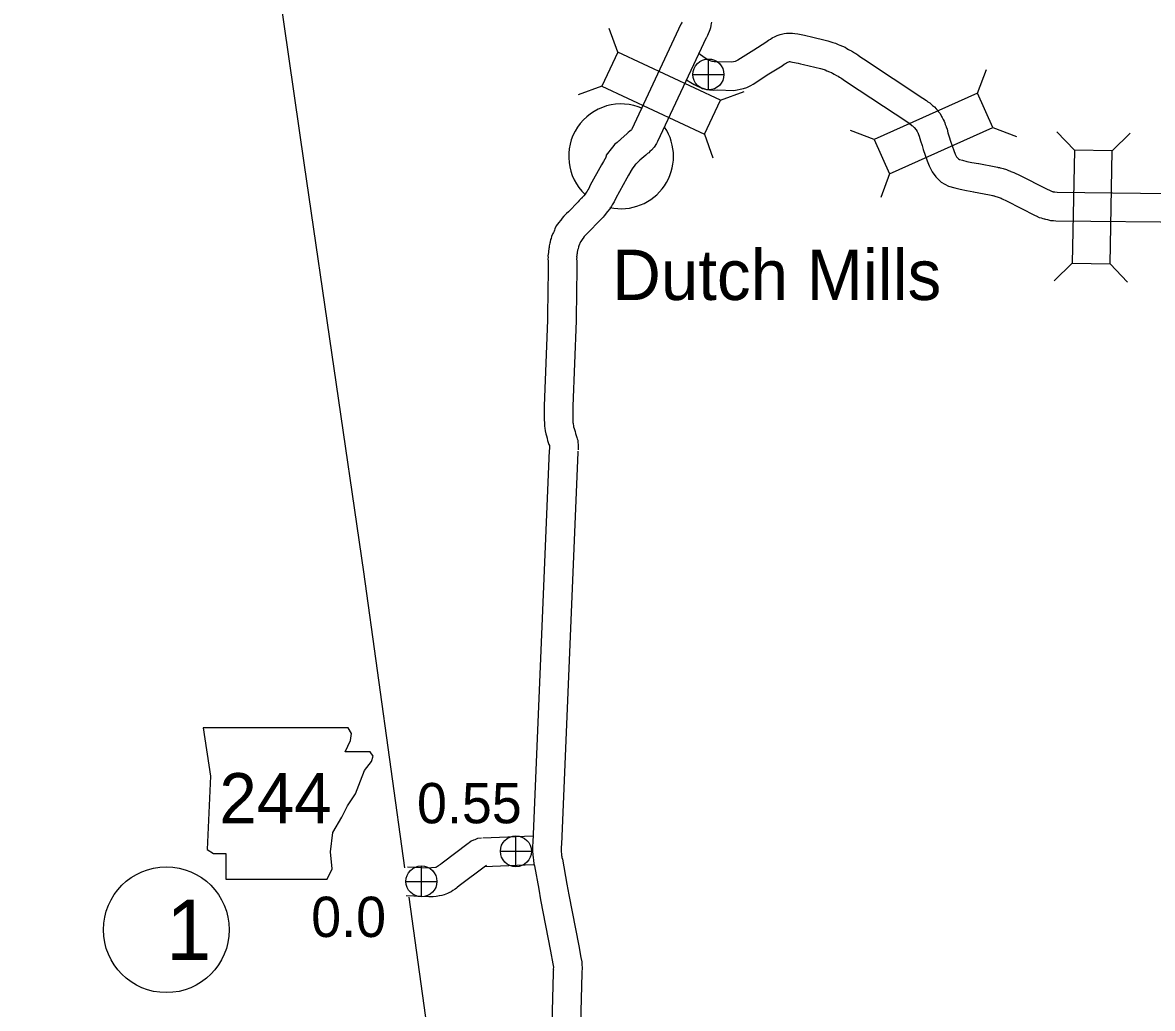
# Model space of a CAD drawing. Extents: x -939622 to -934245, y 1383184 to 1385301.
# Drawn here: x -936492.99 to -936457.42, y 1384824.91 to 1384855.94 of the extents above; entities that cross this region are included whole.
import ezdxf

# ---------------------------------------------------------------- set-up
doc = ezdxf.new("R2010")
doc.units = 0
for name, color, linetype in [('1', 7, 'Continuous'), ('10', 7, 'Continuous'), ('20', 7, 'Continuous'), ('21', 7, 'Continuous'), ('24', 7, 'Continuous'), ('25', 7, 'Continuous'), ('26', 7, 'Continuous'), ('27', 7, 'Continuous')]:
    doc.layers.add(name, color=color, linetype=linetype)

msp = doc.modelspace()

# ---------------------------------------------------------------- linework, layer by layer
at = {"layer": '1'}
for points in [[(-936484.111, 1384851.453), (-936491.245, 1384900.95), (-936492.986, 1384912.484)], [(-936480.949, 1384829.338), (-936482.239, 1384838.65), (-936484.111, 1384851.453)], [(-936478.373, 1384810.747), (-936480.821, 1384828.415)]]:
    msp.add_lwpolyline(points, dxfattribs=at)
at = {"layer": '10'}
for points in [[(-936472.227, 1384855.956), (-936472.234, 1384855.942), (-936472.239, 1384855.933), (-936472.262, 1384855.897), (-936473.811, 1384852.588), (-936473.82, 1384852.57), (-936473.83, 1384852.562), (-936473.873, 1384852.523), (-936473.922, 1384852.48), (-936473.966, 1384852.437), (-936474.145, 1384852.286), (-936474.211, 1384852.226), (-936474.231, 1384852.206), (-936474.27, 1384852.172), (-936474.338, 1384852.113), (-936474.412, 1384852.023), (-936474.615, 1384851.765), (-936474.629, 1384851.702)], [(-936471.299, 1384855.956), (-936471.306, 1384855.916), (-936471.317, 1384855.851), (-936471.336, 1384855.776), (-936471.356, 1384855.711), (-936471.376, 1384855.66), (-936471.402, 1384855.595), (-936471.431, 1384855.536), (-936471.461, 1384855.478), (-936471.473, 1384855.46), (-936472.998, 1384852.202), (-936473.031, 1384852.134), (-936473.1, 1384852.017), (-936473.19, 1384851.924), (-936473.239, 1384851.883), (-936473.278, 1384851.848), (-936473.312, 1384851.818), (-936473.363, 1384851.769), (-936473.551, 1384851.609), (-936473.586, 1384851.578), (-936473.614, 1384851.549), (-936473.681, 1384851.492), (-936473.69, 1384851.484), (-936473.71, 1384851.459), (-936473.737, 1384851.424), (-936473.774, 1384851.372), (-936473.777, 1384851.369), (-936473.846, 1384851.256)], [(-936471.684, 1384854.97), (-936471.65, 1384854.943), (-936471.575, 1384854.884), (-936471.466, 1384854.816), (-936471.413, 1384854.781), (-936471.376, 1384854.765), (-936471.326, 1384854.742), (-936471.285, 1384854.729), (-936471.273, 1384854.726), (-936471.212, 1384854.721), (-936471.107, 1384854.722), (-936470.668, 1384854.709), (-936470.543, 1384854.734), (-936470.501, 1384854.755), (-936470.485, 1384854.761), (-936470.471, 1384854.77), (-936469.972, 1384855.089), (-936469.588, 1384855.327), (-936469.507, 1384855.389), (-936469.446, 1384855.423), (-936469.393, 1384855.459), (-936469.294, 1384855.508), (-936469.233, 1384855.533), (-936469.135, 1384855.572), (-936469.057, 1384855.59), (-936469.017, 1384855.599), (-936468.937, 1384855.613), (-936468.873, 1384855.614), (-936468.812, 1384855.615), (-936468.746, 1384855.61), (-936468.679, 1384855.602), (-936468.579, 1384855.585), (-936468.373, 1384855.543), (-936468.294, 1384855.524), (-936468.199, 1384855.502), (-936467.635, 1384855.37), (-936467.482, 1384855.322), (-936467.393, 1384855.293), (-936467.314, 1384855.257), (-936467.259, 1384855.235), (-936467.181, 1384855.206), (-936467.097, 1384855.165), (-936467.038, 1384855.131), (-936466.983, 1384855.099), (-936466.943, 1384855.075), (-936466.889, 1384855.05), (-936466.794, 1384854.99), (-936466.755, 1384854.966), (-936466.691, 1384854.927), (-936466.63, 1384854.881), (-936466.516, 1384854.803), (-936464.643, 1384853.568), (-936464.529, 1384853.486), (-936464.489, 1384853.453), (-936464.431, 1384853.421), (-936464.353, 1384853.345), (-936464.343, 1384853.336), (-936464.278, 1384853.289), (-936464.226, 1384853.225), (-936464.18, 1384853.176), (-936464.163, 1384853.15), (-936464.106, 1384853.086), (-936464.056, 1384852.988), (-936464.039, 1384852.953), (-936464.004, 1384852.897), (-936463.979, 1384852.837), (-936463.96, 1384852.783), (-936463.945, 1384852.74), (-936463.928, 1384852.698), (-936463.917, 1384852.67), (-936463.913, 1384852.662)], [(-936472.097, 1384854.149), (-936472.092, 1384854.145), (-936471.953, 1384854.06), (-936471.849, 1384853.99), (-936471.741, 1384853.942), (-936471.646, 1384853.9), (-936471.543, 1384853.867), (-936471.453, 1384853.842), (-936471.368, 1384853.831), (-936471.243, 1384853.82), (-936471.115, 1384853.822), (-936470.594, 1384853.806), (-936470.297, 1384853.865), (-936470.191, 1384853.904), (-936470.123, 1384853.937), (-936470.067, 1384853.962), (-936469.992, 1384854.008), (-936469.493, 1384854.327), (-936469.074, 1384854.586), (-936469.013, 1384854.634), (-936468.973, 1384854.656), (-936468.937, 1384854.681), (-936468.922, 1384854.688), (-936468.894, 1384854.699), (-936468.867, 1384854.71), (-936468.862, 1384854.711), (-936468.849, 1384854.714), (-936468.837, 1384854.714), (-936468.831, 1384854.714), (-936468.808, 1384854.711), (-936468.746, 1384854.7), (-936468.567, 1384854.664), (-936468.501, 1384854.648), (-936468.404, 1384854.626), (-936467.874, 1384854.502), (-936467.756, 1384854.464), (-936467.719, 1384854.452), (-936467.67, 1384854.43), (-936467.581, 1384854.394), (-936467.533, 1384854.376), (-936467.52, 1384854.37), (-936467.488, 1384854.352), (-936467.441, 1384854.325), (-936467.366, 1384854.279), (-936467.318, 1384854.257), (-936467.273, 1384854.229), (-936467.227, 1384854.2), (-936467.195, 1384854.18), (-936467.154, 1384854.15), (-936467.019, 1384854.057), (-936465.154, 1384852.827), (-936465.08, 1384852.774), (-936464.999, 1384852.707), (-936464.974, 1384852.693), (-936464.919, 1384852.644), (-936464.854, 1384852.572), (-936464.828, 1384852.519), (-936464.812, 1384852.493), (-936464.808, 1384852.48), (-936464.786, 1384852.421), (-936464.765, 1384852.368)], [(-936464.765, 1384852.368), (-936464.724, 1384852.223)], [(-936463.913, 1384852.662), (-936463.887, 1384852.587)], [(-936463.887, 1384852.587), (-936463.859, 1384852.476), (-936463.816, 1384852.345), (-936463.777, 1384852.216), (-936463.727, 1384852.067), (-936463.668, 1384851.912), (-936463.625, 1384851.801), (-936463.586, 1384851.723), (-936463.551, 1384851.676), (-936463.529, 1384851.653), (-936463.497, 1384851.636), (-936463.4, 1384851.608), (-936463.262, 1384851.573), (-936463.103, 1384851.538), (-936462.897, 1384851.506)], [(-936464.724, 1384852.223), (-936464.674, 1384852.072), (-936464.634, 1384851.944), (-936464.575, 1384851.765), (-936464.509, 1384851.592), (-936464.45, 1384851.438), (-936464.356, 1384851.25), (-936464.235, 1384851.086), (-936464.07, 1384850.921), (-936463.836, 1384850.798), (-936463.637, 1384850.74), (-936463.47, 1384850.697), (-936463.269, 1384850.653), (-936463.038, 1384850.617)], [(-936474.617, 1384851.72), (-936474.703, 1384851.574), (-936474.758, 1384851.468), (-936475.115, 1384850.829), (-936475.165, 1384850.724), (-936475.193, 1384850.676), (-936475.215, 1384850.642), (-936475.244, 1384850.596), (-936475.281, 1384850.547), (-936475.323, 1384850.494), (-936475.352, 1384850.455), (-936475.369, 1384850.433), (-936475.376, 1384850.426), (-936475.382, 1384850.419), (-936475.416, 1384850.392), (-936475.463, 1384850.339), (-936475.501, 1384850.298), (-936475.805, 1384849.991), (-936475.86, 1384849.931), (-936475.945, 1384849.847), (-936476.008, 1384849.776), (-936476.015, 1384849.767), (-936476.148, 1384849.599), (-936476.185, 1384849.544), (-936476.231, 1384849.455), (-936476.247, 1384849.407), (-936476.257, 1384849.38), (-936476.267, 1384849.355), (-936476.275, 1384849.338), (-936476.298, 1384849.301), (-936476.335, 1384849.209), (-936476.351, 1384849.149), (-936476.364, 1384849.111), (-936476.376, 1384849.04), (-936476.377, 1384849.031), (-936476.385, 1384849.005), (-936476.41, 1384848.916), (-936476.411, 1384848.867), (-936476.411, 1384848.866), (-936476.417, 1384848.835), (-936476.423, 1384848.791), (-936476.426, 1384848.77), (-936476.436, 1384848.709), (-936476.448, 1384848.604), (-936476.445, 1384848.552), (-936476.449, 1384848.509), (-936476.443, 1384848.435), (-936476.44, 1384848.395), (-936476.44, 1384848.385), (-936476.452, 1384847.23), (-936476.449, 1384847.192), (-936476.45, 1384847.133), (-936476.46, 1384847.07), (-936476.462, 1384846.878), (-936476.459, 1384846.824), (-936476.459, 1384846.802), (-936476.463, 1384846.739), (-936476.464, 1384846.657), (-936476.465, 1384846.576), (-936476.565, 1384843.875), (-936476.563, 1384843.776), (-936476.564, 1384843.687), (-936476.565, 1384843.618), (-936476.566, 1384843.559), (-936476.563, 1384843.52), (-936476.564, 1384843.443), (-936476.562, 1384843.341), (-936476.557, 1384843.24), (-936476.543, 1384843.175), (-936476.535, 1384843.096), (-936476.512, 1384842.995), (-936476.496, 1384842.939), (-936476.477, 1384842.864), (-936476.471, 1384842.848), (-936476.463, 1384842.792), (-936476.439, 1384842.722), (-936476.419, 1384842.66), (-936476.404, 1384842.627), (-936476.399, 1384842.611), (-936476.399, 1384842.6), (-936476.4, 1384842.567), (-936476.4, 1384842.546), (-936476.4, 1384842.507)], [(-936473.842, 1384851.262), (-936473.915, 1384851.14), (-936473.964, 1384851.043), (-936474.315, 1384850.417), (-936474.369, 1384850.301), (-936474.426, 1384850.206), (-936474.453, 1384850.162), (-936474.503, 1384850.084), (-936474.569, 1384849.996), (-936474.613, 1384849.941), (-936474.637, 1384849.909), (-936474.675, 1384849.859), (-936474.711, 1384849.819), (-936474.772, 1384849.754), (-936474.798, 1384849.734), (-936474.846, 1384849.68), (-936475.154, 1384849.369), (-936475.213, 1384849.304), (-936475.292, 1384849.227), (-936475.308, 1384849.209), (-936475.311, 1384849.205), (-936475.343, 1384849.154), (-936475.352, 1384849.142), (-936475.41, 1384849.053), (-936475.42, 1384849.046), (-936475.444, 1384848.992), (-936475.454, 1384848.969), (-936475.479, 1384848.914), (-936475.481, 1384848.91), (-936475.488, 1384848.89), (-936475.49, 1384848.883), (-936475.501, 1384848.826), (-936475.515, 1384848.775), (-936475.524, 1384848.709), (-936475.53, 1384848.681), (-936475.531, 1384848.677), (-936475.535, 1384848.644), (-936475.544, 1384848.586), (-936475.545, 1384848.576), (-936475.543, 1384848.533), (-936475.546, 1384848.503), (-936475.539, 1384848.431), (-936475.54, 1384848.375), (-936475.552, 1384847.256), (-936475.545, 1384847.156), (-936475.55, 1384847.111), (-936475.551, 1384847.059), (-936475.557, 1384847.017), (-936475.559, 1384846.883), (-936475.56, 1384846.872), (-936475.559, 1384846.84), (-936475.56, 1384846.772), (-936475.563, 1384846.709), (-936475.564, 1384846.647), (-936475.565, 1384846.554), (-936475.665, 1384843.868), (-936475.663, 1384843.781), (-936475.664, 1384843.678), (-936475.665, 1384843.609), (-936475.665, 1384843.584), (-936475.663, 1384843.545), (-936475.664, 1384843.448), (-936475.662, 1384843.37), (-936475.661, 1384843.358), (-936475.653, 1384843.32), (-936475.645, 1384843.243), (-936475.639, 1384843.217), (-936475.626, 1384843.171), (-936475.616, 1384843.131), (-936475.593, 1384843.069), (-936475.584, 1384843.005), (-936475.576, 1384842.98), (-936475.562, 1384842.947), (-936475.552, 1384842.915), (-936475.536, 1384842.878), (-936475.526, 1384842.836), (-936475.513, 1384842.796), (-936475.504, 1384842.725), (-936475.498, 1384842.663), (-936475.499, 1384842.59), (-936475.5, 1384842.557), (-936475.5, 1384842.536), (-936475.5, 1384842.497)], [(-936462.885, 1384851.504), (-936462.348, 1384851.404), (-936462.299, 1384851.391), (-936462.272, 1384851.386), (-936462.236, 1384851.377), (-936462.214, 1384851.372), (-936462.161, 1384851.361), (-936462.117, 1384851.346), (-936462.013, 1384851.315), (-936461.955, 1384851.288), (-936461.924, 1384851.28), (-936461.893, 1384851.267), (-936461.875, 1384851.261), (-936461.845, 1384851.249), (-936461.785, 1384851.223), (-936461.743, 1384851.2), (-936461.629, 1384851.148), (-936460.733, 1384850.695), (-936460.662, 1384850.665), (-936460.576, 1384850.631), (-936460.575, 1384850.631), (-936460.545, 1384850.622), (-936460.544, 1384850.621), (-936460.542, 1384850.621), (-936460.534, 1384850.619), (-936460.496, 1384850.613), (-936460.414, 1384850.601), (-936456.05, 1384850.556)], [(-936463.05, 1384850.619), (-936462.544, 1384850.525), (-936462.498, 1384850.513), (-936462.459, 1384850.505), (-936462.441, 1384850.501), (-936462.41, 1384850.494), (-936462.402, 1384850.492), (-936462.379, 1384850.484), (-936462.278, 1384850.443), (-936462.21, 1384850.425), (-936462.194, 1384850.419), (-936462.182, 1384850.414), (-936462.147, 1384850.395), (-936462.017, 1384850.336), (-936461.109, 1384849.876), (-936461.076, 1384849.863), (-936460.985, 1384849.81), (-936460.918, 1384849.798), (-936460.873, 1384849.78), (-936460.832, 1384849.768), (-936460.82, 1384849.765), (-936460.785, 1384849.752), (-936460.728, 1384849.74), (-936460.624, 1384849.718), (-936460.581, 1384849.718), (-936460.539, 1384849.712), (-936460.466, 1384849.702), (-936456.063, 1384849.656)], [(-936476.397, 1384842.551), (-936476.401, 1384842.524), (-936476.406, 1384842.482), (-936476.926, 1384830.135), (-936476.933, 1384830.026), (-936476.935, 1384829.921), (-936476.932, 1384829.84), (-936476.928, 1384829.771), (-936476.92, 1384829.717), (-936476.917, 1384829.689), (-936476.915, 1384829.656), (-936476.907, 1384829.581), (-936476.89, 1384829.461), (-936476.87, 1384829.397), (-936476.737, 1384828.662), (-936476.68, 1384828.328), (-936476.364, 1384826.712), (-936476.294, 1384826.316), (-936476.28, 1384826.262), (-936476.276, 1384826.213), (-936476.282, 1384826.148), (-936476.279, 1384826.117), (-936476.281, 1384826.097), (-936476.281, 1384826.022), (-936476.724, 1384809.353)], [(-936475.503, 1384842.452), (-936475.507, 1384842.42), (-936475.508, 1384842.408), (-936476.027, 1384830.085), (-936476.034, 1384829.99), (-936476.034, 1384829.932), (-936476.033, 1384829.881), (-936476.031, 1384829.86), (-936476.028, 1384829.836), (-936476.02, 1384829.774), (-936476.017, 1384829.728), (-936476.014, 1384829.69), (-936476.009, 1384829.659), (-936475.994, 1384829.609), (-936475.85, 1384828.817), (-936475.794, 1384828.49), (-936475.48, 1384826.877), (-936475.414, 1384826.51), (-936475.381, 1384826.381), (-936475.381, 1384826.315), (-936475.38, 1384826.3), (-936475.371, 1384826.182), (-936475.381, 1384826.056), (-936475.382, 1384826.005), (-936475.825, 1384809.294)], [(-936478.536, 1384830.274), (-936478.665, 1384830.257), (-936478.749, 1384830.222), (-936478.787, 1384830.208), (-936478.862, 1384830.171), (-936478.929, 1384830.124), (-936478.962, 1384830.099), (-936479.78, 1384829.484), (-936479.834, 1384829.443), (-936479.87, 1384829.418), (-936479.891, 1384829.401), (-936479.928, 1384829.377), (-936479.957, 1384829.359), (-936479.963, 1384829.356), (-936479.964, 1384829.356), (-936479.982, 1384829.348), (-936479.984, 1384829.347), (-936480.111, 1384829.335), (-936480.183, 1384829.326), (-936480.868, 1384829.356)], [(-936478.497, 1384830.277), (-936476.923, 1384830.343)], [(-936478.385, 1384829.407), (-936478.415, 1384829.383), (-936479.24, 1384828.764), (-936479.306, 1384828.714), (-936479.33, 1384828.697), (-936479.368, 1384828.667), (-936479.445, 1384828.618), (-936479.5, 1384828.583), (-936479.572, 1384828.544), (-936479.614, 1384828.526), (-936479.667, 1384828.504), (-936479.715, 1384828.488), (-936479.792, 1384828.464), (-936479.858, 1384828.455), (-936479.873, 1384828.454), (-936479.912, 1384828.446), (-936479.967, 1384828.436), (-936480.062, 1384828.425), (-936480.063, 1384828.425), (-936480.2, 1384828.426), (-936480.908, 1384828.457)], [(-936478.46, 1384829.378), (-936476.906, 1384829.443)]]:
    msp.add_lwpolyline(points, dxfattribs=at)
at = {"layer": '20'}
for p, q in [((-936474.248, 1384855.014), (-936474.518, 1384855.759)), ((-936462.929, 1384853.721), (-936462.648, 1384854.462)), ((-936474.752, 1384853.938), (-936475.496, 1384853.668)), ((-936471.02, 1384853.503), (-936470.276, 1384853.773)), ((-936471.524, 1384852.427), (-936471.254, 1384851.682)), ((-936466.18, 1384852.261), (-936466.92, 1384852.543)), ((-936462.442, 1384852.638), (-936461.702, 1384852.356)), ((-936459.877, 1384851.931), (-936460.427, 1384852.501)), ((-936458.689, 1384851.909), (-936458.119, 1384852.459)), ((-936465.694, 1384851.178), (-936465.975, 1384850.437)), ((-936459.942, 1384848.367), (-936460.512, 1384847.818)), ((-936458.754, 1384848.346), (-936458.204, 1384847.776))]:
    msp.add_line(p, q, dxfattribs=at)
for points in [[(-936474.752, 1384853.938), (-936471.524, 1384852.427), (-936471.02, 1384853.503), (-936474.248, 1384855.014)], [(-936462.929, 1384853.721), (-936466.18, 1384852.261), (-936465.694, 1384851.178), (-936462.442, 1384852.638)], [(-936458.754, 1384848.346), (-936458.689, 1384851.909), (-936459.877, 1384851.931), (-936459.942, 1384848.367)]]:
    msp.add_lwpolyline(points, close=True, dxfattribs=at)
at = {"layer": '21'}
msp.add_lwpolyline([(-936487.303, 1384833.745), (-936487.074, 1384832.222), (-936487.176, 1384829.913), (-936486.973, 1384829.786), (-936486.592, 1384829.786), (-936486.592, 1384828.974), (-936483.395, 1384828.974), (-936483.242, 1384829.304), (-936483.293, 1384829.837), (-936483.217, 1384830.446), (-936482.938, 1384830.928), (-936482.76, 1384831.283), (-936482.506, 1384831.664), (-936482.354, 1384832.07), (-936482.227, 1384832.4), (-936481.999, 1384832.679), (-936481.948, 1384832.856), (-936482.05, 1384832.983), (-936482.836, 1384832.983), (-936482.659, 1384833.339), (-936482.633, 1384833.567), (-936482.738, 1384833.742)], close=True, dxfattribs=at)
at = {"layer": '24'}
for start, end in [(65.7338, 226.9065), (257.7489, 33.824)]:
    msp.add_arc((-936474.146, 1384851.734), 1.65, start, end, dxfattribs=at)
at = {"layer": '26'}
for p, q in [((-936471.396, 1384853.822), (-936471.396, 1384854.797)), ((-936471.884, 1384854.31), (-936470.909, 1384854.31)), ((-936477.457, 1384829.368), (-936477.457, 1384830.343)), ((-936477.944, 1384829.856), (-936476.969, 1384829.856)), ((-936480.431, 1384828.422), (-936480.431, 1384829.397)), ((-936480.919, 1384828.909), (-936479.944, 1384828.909))]:
    msp.add_line(p, q, dxfattribs=at)
for centre in [(-936471.396, 1384854.31), (-936477.457, 1384829.856), (-936480.431, 1384828.909)]:
    msp.add_circle(centre, 0.487, dxfattribs=at)
at = {"layer": '27'}
msp.add_circle((-936488.461, 1384827.387), 1.98, dxfattribs=at)

# ---------------------------------------------------------------- texts
at = {"layer": '21'}
msp.add_text('244', height=1.584, dxfattribs=at).set_placement((-936486.792, 1384830.734))
at = {"layer": '24'}
msp.add_text('Dutch Mills', height=1.584, dxfattribs=at).set_placement((-936474.425, 1384847.211))
at = {"layer": '25'}
for s, p in [('0.55', (-936480.571, 1384830.738)), ('0.0', (-936483.9, 1384827.159))]:
    msp.add_text(s, height=1.2672, dxfattribs=at).set_placement(p)
at = {"layer": '27'}
msp.add_text('1', height=1.901, rotation=359.9, dxfattribs=at).set_placement((-936488.463, 1384826.437))

doc.saveas('drawing.dxf')
